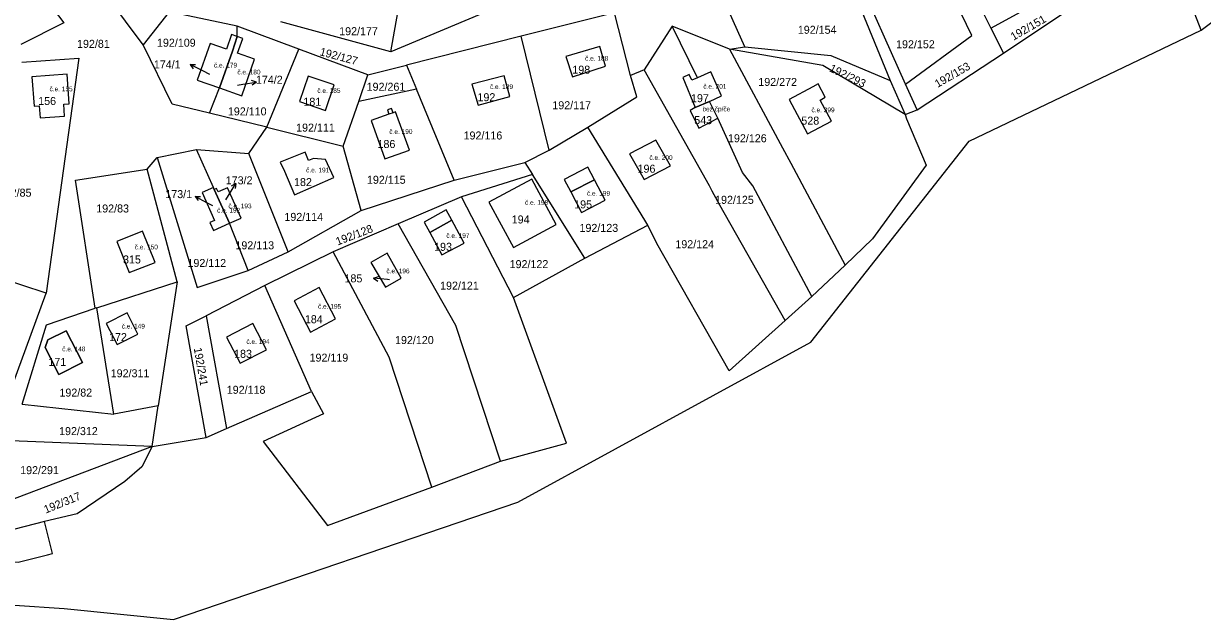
# Model space of a CAD drawing. Extents: x -887272 to -880188, y -1026687 to -1021896.
# Drawn here: x -882333.3 to -882082.9, y -1024320.7 to -1024194 of the extents above; entities that cross this region are included whole.
import ezdxf

# ---------------------------------------------------------------- set-up
doc = ezdxf.new("R2010")
doc.units = 0
for name, color, linetype in [('Definiční body', 7, 'Continuous'), ('Hranice parcel', 7, 'Continuous'), ('Parcelní čísla', 7, 'Continuous'), ('Polygon budovy', 7, 'Continuous'), ('Pop  PČ popisy', 7, 'Continuous'), ('Vnitřní kresba', 7, 'Continuous')]:
    doc.layers.add(name, color=color, linetype=linetype)

msp = doc.modelspace()

# ---------------------------------------------------------------- linework, layer by layer
at = {"layer": 'Hranice parcel'}
for p, q in [((-882137.35, -1024175.98), (-882127.83, -1024194.96)), ((-882083.16, -1024195.4), (-882090.34, -1024176.88)), ((-882255.25, -1024200.01), (-882252.31, -1024183.68)), ((-882127.83, -1024194.96), (-882110.47, -1024185.49)), ((-882083.16, -1024195.4), (-882069.52, -1024185.2)), ((-882307.87, -1024198.55), (-882315.45, -1024188.28)), ((-882125.14, -1024200.32), (-882108.68, -1024189.29)), ((-882255.25, -1024200.01), (-882278.63, -1024193.63)), ((-882236.46, -1024192.13), (-882255.25, -1024200.01)), ((-882207.74, -1024191.74), (-882227.58, -1024196.72)), ((-882204.37, -1024205.08), (-882207.74, -1024191.74)), ((-882287.91, -1024196.76), (-882287.91, -1024194.55)), ((-882274.77, -1024199.44), (-882287.91, -1024194.55)), ((-882195.51, -1024194.55), (-882201.44, -1024203.82)), ((-882183.3, -1024199.45), (-882195.51, -1024194.55)), ((-882190.09, -1024205.51), (-882195.51, -1024194.55)), ((-882127.83, -1024194.96), (-882125.14, -1024200.32)), ((-882227.58, -1024196.72), (-882251.93, -1024202.84)), ((-882221.64, -1024220.93), (-882227.58, -1024196.72)), ((-882183.3, -1024199.45), (-882180.08, -1024198.94)), ((-882333.65, -1024202.21), (-882321.52, -1024201.38)), ((-882321.52, -1024201.38), (-882328.48, -1024251.3)), ((-882281.59, -1024216.03), (-882274.77, -1024199.44)), ((-882260.11, -1024204.89), (-882274.77, -1024199.44)), ((-882143.48, -1024212.36), (-882125.14, -1024200.32)), ((-882260.11, -1024204.89), (-882251.93, -1024202.84)), ((-882251.93, -1024202.84), (-882249.83, -1024207.92)), ((-882201.44, -1024203.82), (-882204.37, -1024205.08)), ((-882262.06, -1024210.54), (-882260.11, -1024204.89)), ((-882149.19, -1024206.14), (-882145.98, -1024213.34)), ((-882293.75, -1024213.08), (-882291.66, -1024207.69)), ((-882249.83, -1024207.92), (-882262.06, -1024210.54)), ((-882241.79, -1024227.32), (-882249.83, -1024207.92)), ((-882143.48, -1024212.36), (-882145.92, -1024206.9)), ((-882265.36, -1024220.09), (-882262.06, -1024210.54)), ((-882190.63, -1024211.87), (-882187.6, -1024210.54)), ((-882185.83, -1024214.12), (-882187.6, -1024210.54)), ((-882281.59, -1024216.03), (-882293.75, -1024213.08)), ((-882145.98, -1024213.34), (-882143.48, -1024212.36)), ((-882145.98, -1024213.34), (-882145.75, -1024214.26)), ((-882285.44, -1024221.62), (-882281.59, -1024216.03)), ((-882281.59, -1024216.03), (-882265.36, -1024220.09)), ((-882221.64, -1024220.93), (-882213.38, -1024216.04)), ((-882180.56, -1024225.66), (-882185.83, -1024214.12)), ((-882304.86, -1024222.45), (-882296.53, -1024220.75)), ((-882292.94, -1024228.83), (-882296.53, -1024220.75)), ((-882296.53, -1024220.75), (-882285.44, -1024221.62)), ((-882261.58, -1024233.71), (-882265.36, -1024220.09)), ((-882226.76, -1024223.54), (-882221.64, -1024220.93)), ((-882307, -1024224.99), (-882304.86, -1024222.45)), ((-882277.04, -1024242.53), (-882285.44, -1024221.62)), ((-882241.79, -1024227.32), (-882226.76, -1024223.54)), ((-882226.76, -1024223.54), (-882225.17, -1024226.09)), ((-882300.66, -1024248.91), (-882307, -1024224.99)), ((-882225.17, -1024226.09), (-882240.26, -1024230.81)), ((-882214.06, -1024243.9), (-882225.17, -1024226.09)), ((-882292.75, -1024229.25), (-882292.94, -1024228.83)), ((-882261.58, -1024233.71), (-882241.79, -1024227.32)), ((-882289.52, -1024236.46), (-882292.75, -1024229.25)), ((-882240.26, -1024230.81), (-882253.67, -1024236.56)), ((-882229.17, -1024252.22), (-882240.26, -1024230.81)), ((-882277.04, -1024242.53), (-882261.58, -1024233.71)), ((-882285.58, -1024246.47), (-882289.52, -1024236.46)), ((-882253.67, -1024236.56), (-882267.53, -1024242.5)), ((-882214.06, -1024243.9), (-882200.68, -1024236.89)), ((-882285.58, -1024246.47), (-882277.04, -1024242.53)), ((-882267.53, -1024242.5), (-882282.01, -1024249.71)), ((-882229.17, -1024252.22), (-882214.06, -1024243.9)), ((-882158.78, -1024245.34), (-882165.85, -1024252.03)), ((-882328.48, -1024251.3), (-882341.03, -1024247.16)), ((-882317.71, -1024254.4), (-882300.66, -1024248.91)), ((-882300.66, -1024248.91), (-882304.64, -1024275.27)), ((-882339.9, -1024282.5), (-882328.48, -1024251.3)), ((-882282.01, -1024249.71), (-882294.5, -1024256.1)), ((-882272.1, -1024272.18), (-882282.01, -1024249.71)), ((-882165.85, -1024252.03), (-882171.52, -1024257.13)), ((-882317.71, -1024254.4), (-882318.06, -1024254.51)), ((-882314.06, -1024277.04), (-882317.71, -1024254.4)), ((-882294.5, -1024256.1), (-882290.13, -1024280.09)), ((-882287.25, -1024266.21), (-882281.69, -1024263.34)), ((-882290.13, -1024280.09), (-882272.1, -1024272.18)), ((-882333.57, -1024274.9), (-882314.06, -1024277.04)), ((-882304.64, -1024275.27), (-882314.06, -1024277.04)), ((-882305.94, -1024283.91), (-882304.64, -1024275.27)), ((-882294.5, -1024282), (-882290.13, -1024280.09)), ((-882305.94, -1024283.91), (-882340.7, -1024297.09)), ((-882305.94, -1024283.91), (-882335.99, -1024282.71)), ((-882305.94, -1024283.91), (-882294.5, -1024282)), ((-882246.57, -1024292.54), (-882231.98, -1024287))]:
    msp.add_line(p, q, dxfattribs=at)
for points in [[(-882180.08, -1024198.94), (-882186.61, -1024184.38), (-882170.75, -1024175.81), (-882159.27, -1024181.5), (-882149.19, -1024206.14)], [(-882145.92, -1024206.9), (-882156.65, -1024182.88), (-882141.11, -1024177.32)], [(-882145.92, -1024206.9), (-882131.84, -1024196.57), (-882141.11, -1024177.32)], [(-882334.7, -1024180.71), (-882324.68, -1024193.85), (-882333.83, -1024198.49)], [(-882287.91, -1024194.55), (-882302.33, -1024191.49), (-882307.87, -1024198.55)], [(-882425.59, -1024292.38), (-882421.44, -1024309.52), (-882387.34, -1024318.62), (-882335.2, -1024317.62), (-882324.6, -1024318.36), (-882301.38, -1024320.66), (-882228.26, -1024295.72), (-882166.04, -1024261.72), (-882132.4, -1024219.02), (-882083.16, -1024195.4)], [(-882287.91, -1024196.76), (-882289.09, -1024196.35), (-882290.17, -1024199.42), (-882293.65, -1024198.24), (-882296.39, -1024206.02), (-882291.66, -1024207.69)], [(-882293.75, -1024213.08), (-882301.69, -1024211.15), (-882307.87, -1024198.55)], [(-882291.66, -1024207.69), (-882288.91, -1024199.91), (-882287.91, -1024196.76)], [(-882291.66, -1024207.69), (-882286.93, -1024209.36), (-882284.18, -1024201.58), (-882287.81, -1024200.29), (-882286.72, -1024197.18), (-882287.91, -1024196.76)], [(-882210.86, -1024198.88), (-882218.06, -1024201), (-882216.7, -1024205.32), (-882209.64, -1024203.1), (-882210.86, -1024198.88)], [(-882180.08, -1024198.94), (-882161.77, -1024200.83), (-882149.19, -1024206.14)], [(-882145.98, -1024213.34), (-882163.48, -1024202.95), (-882183.3, -1024199.45)], [(-882183.3, -1024199.45), (-882172.08, -1024220.45), (-882170.3, -1024223.69), (-882158.78, -1024245.34)], [(-882171.52, -1024257.13), (-882185.35, -1024232.63), (-882186.97, -1024229.61), (-882187.58, -1024228.52), (-882201.44, -1024203.82)], [(-882324.73, -1024211.15), (-882323.57, -1024211.07), (-882324.01, -1024204.8), (-882331.48, -1024205.32), (-882331.04, -1024211.59), (-882329.92, -1024211.51), (-882329.75, -1024214.03), (-882324.56, -1024213.66), (-882324.73, -1024211.15)], [(-882269.12, -1024212.48), (-882267.28, -1024207.04), (-882272.82, -1024205.16), (-882274.66, -1024210.6), (-882269.12, -1024212.48)], [(-882238.06, -1024206.92), (-882236.68, -1024211.34), (-882229.98, -1024209.54), (-882231.17, -1024205.1), (-882238.06, -1024206.92)], [(-882213.38, -1024216.04), (-882203.01, -1024209.61), (-882204.37, -1024205.08)], [(-882190.09, -1024205.51), (-882191.34, -1024206.06), (-882191.87, -1024204.86), (-882193.25, -1024205.47), (-882190.63, -1024211.87)], [(-882187.6, -1024210.54), (-882185, -1024209.4), (-882187.26, -1024204.26), (-882190.09, -1024205.51)], [(-882164.08, -1024210.28), (-882162.97, -1024209.68), (-882164.51, -1024206.83), (-882165.62, -1024207.44), (-882170.68, -1024210.17), (-882166.73, -1024217.47), (-882161.67, -1024214.72), (-882164.08, -1024210.28)], [(-882251.3, -1024220.9), (-882254.23, -1024212.75), (-882254.79, -1024212.95), (-882255.11, -1024212.06), (-882255.98, -1024212.38), (-882255.66, -1024213.27), (-882259.45, -1024214.63), (-882256.52, -1024222.78), (-882251.3, -1024220.9)], [(-882190.63, -1024211.87), (-882191.71, -1024212.5), (-882189.8, -1024216.26), (-882185.83, -1024214.12)], [(-882200.68, -1024236.89), (-882201.33, -1024235.82), (-882213.38, -1024216.04)], [(-882145.75, -1024214.26), (-882141.56, -1024224.13), (-882152.95, -1024239.76), (-882158.78, -1024245.34)], [(-882201.44, -1024227.17), (-882195.88, -1024224.22), (-882199, -1024218.76), (-882204.57, -1024221.7), (-882201.44, -1024227.17)], [(-882272.74, -1024223.14), (-882273.48, -1024221.33), (-882278.76, -1024223.45), (-882277.87, -1024225.35), (-882275.68, -1024230.39), (-882267.34, -1024226.76), (-882269.11, -1024222.93), (-882271.67, -1024222.67), (-882272.74, -1024223.14)], [(-882304.86, -1024222.45), (-882296.39, -1024250.09), (-882285.58, -1024246.47)], [(-882318.06, -1024254.51), (-882322.2, -1024227.27), (-882307, -1024224.99)], [(-882212, -1024227.22), (-882213.39, -1024224.56), (-882218.41, -1024227.12), (-882217.04, -1024229.79), (-882214.79, -1024234.19), (-882209.75, -1024231.53), (-882212, -1024227.22)], [(-882165.85, -1024252.03), (-882178.37, -1024228.51), (-882180.56, -1024225.66)], [(-882292.94, -1024228.83), (-882295.35, -1024229.9), (-882292.71, -1024235.84), (-882293.66, -1024236.26), (-882292.91, -1024237.96), (-882289.52, -1024236.46)], [(-882289.52, -1024236.46), (-882287.04, -1024235.36), (-882289.91, -1024228.89), (-882291.94, -1024229.79), (-882292.27, -1024229.04), (-882292.75, -1024229.25)], [(-882229.23, -1024241.61), (-882220.13, -1024236.69), (-882225.33, -1024227.08), (-882234.44, -1024231.98), (-882229.23, -1024241.61)], [(-882246.98, -1024238.4), (-882244.42, -1024243.2), (-882239.66, -1024240.66), (-882242.29, -1024235.83), (-882243.49, -1024233.63), (-882248.15, -1024236.2), (-882246.98, -1024238.4)], [(-882313.46, -1024240.32), (-882310.8, -1024246.9), (-882305.32, -1024244.78), (-882307.99, -1024238.11), (-882313.46, -1024240.32)], [(-882231.98, -1024287), (-882241.44, -1024258.19), (-882253.67, -1024236.56)], [(-882171.52, -1024257.13), (-882183.4, -1024267.82), (-882198.74, -1024240.75), (-882200.68, -1024236.89)], [(-882246.57, -1024292.54), (-882255.59, -1024264.95), (-882267.53, -1024242.5)], [(-882259.52, -1024244.82), (-882256.38, -1024250.06), (-882253.04, -1024248.16), (-882256.04, -1024242.8), (-882259.52, -1024244.82)], [(-882272.32, -1024259.58), (-882266.97, -1024256.76), (-882270.46, -1024250.13), (-882275.81, -1024252.95), (-882272.32, -1024259.58)], [(-882231.98, -1024287), (-882217.96, -1024283.21), (-882229.17, -1024252.22)], [(-882333.57, -1024274.9), (-882328.36, -1024258.07), (-882318.06, -1024254.51)], [(-882308.98, -1024260.01), (-882311.25, -1024255.5), (-882315.71, -1024257.75), (-882313.39, -1024262.23), (-882308.98, -1024260.01)], [(-882294.5, -1024282), (-882298.74, -1024258.26), (-882294.5, -1024256.1)], [(-882281.69, -1024263.34), (-882284.56, -1024257.78), (-882290.12, -1024260.65), (-882287.25, -1024266.21)], [(-882320.76, -1024266.08), (-882325.76, -1024268.62), (-882328.68, -1024262.86), (-882328.13, -1024261.26), (-882324.19, -1024259.33), (-882320.76, -1024266.08)], [(-882272.1, -1024272.18), (-882269.56, -1024276.98), (-882282.34, -1024282.85), (-882268.67, -1024300.71), (-882246.57, -1024292.54)], [(-882305.94, -1024283.91), (-882308.16, -1024288.24), (-882311.77, -1024291.31), (-882321.85, -1024298.23), (-882328.81, -1024299.87)], [(-882354.68, -1024304.32), (-882351.37, -1024305.83), (-882343, -1024308.06), (-882334.42, -1024308.5), (-882328.14, -1024306.91), (-882327.09, -1024306.65), (-882328.81, -1024299.87)], [(-882328.81, -1024299.87), (-882335.11, -1024301.46), (-882341.68, -1024300.07)]]:
    msp.add_lwpolyline(points, dxfattribs=at)
at = {"layer": 'Polygon budovy'}
for points in [[(-882293.65, -1024198.24), (-882296.39, -1024206.02), (-882291.66, -1024207.69), (-882288.91, -1024199.91), (-882287.91, -1024196.76), (-882289.09, -1024196.35), (-882290.17, -1024199.42)], [(-882291.66, -1024207.69), (-882286.93, -1024209.36), (-882284.18, -1024201.58), (-882287.81, -1024200.29), (-882286.72, -1024197.18), (-882287.91, -1024196.76), (-882288.91, -1024199.91)], [(-882218.06, -1024201), (-882216.7, -1024205.32), (-882209.64, -1024203.1), (-882210.86, -1024198.88)], [(-882331.04, -1024211.59), (-882329.92, -1024211.51), (-882329.75, -1024214.03), (-882324.56, -1024213.66), (-882324.73, -1024211.15), (-882323.57, -1024211.07), (-882324.01, -1024204.8), (-882331.48, -1024205.32)], [(-882267.28, -1024207.04), (-882272.82, -1024205.16), (-882274.66, -1024210.6), (-882269.12, -1024212.48)], [(-882229.98, -1024209.54), (-882231.17, -1024205.1), (-882238.06, -1024206.92), (-882236.68, -1024211.34)], [(-882190.09, -1024205.51), (-882191.34, -1024206.06), (-882191.87, -1024204.86), (-882193.25, -1024205.47), (-882190.63, -1024211.87), (-882187.6, -1024210.54), (-882185, -1024209.4), (-882187.26, -1024204.26)], [(-882170.68, -1024210.17), (-882166.73, -1024217.47), (-882161.67, -1024214.72), (-882164.08, -1024210.28), (-882162.97, -1024209.68), (-882164.51, -1024206.83), (-882165.62, -1024207.44)], [(-882190.63, -1024211.87), (-882191.71, -1024212.5), (-882189.8, -1024216.26), (-882185.83, -1024214.12), (-882187.6, -1024210.54)], [(-882259.45, -1024214.63), (-882256.52, -1024222.78), (-882251.3, -1024220.9), (-882254.23, -1024212.75), (-882254.79, -1024212.95), (-882255.66, -1024213.27)], [(-882195.88, -1024224.22), (-882199, -1024218.76), (-882204.57, -1024221.7), (-882201.44, -1024227.17)], [(-882271.67, -1024222.67), (-882272.74, -1024223.14), (-882273.48, -1024221.33), (-882278.76, -1024223.45), (-882277.87, -1024225.35), (-882275.68, -1024230.39), (-882267.34, -1024226.76), (-882269.11, -1024222.93)], [(-882292.91, -1024237.96), (-882289.52, -1024236.46), (-882292.75, -1024229.25), (-882292.94, -1024228.83), (-882295.35, -1024229.9), (-882292.71, -1024235.84), (-882293.66, -1024236.26)], [(-882292.75, -1024229.25), (-882289.52, -1024236.46), (-882287.04, -1024235.36), (-882289.91, -1024228.89), (-882291.94, -1024229.79), (-882292.27, -1024229.04)], [(-882234.44, -1024231.98), (-882229.23, -1024241.61), (-882220.13, -1024236.69), (-882225.33, -1024227.08)], [(-882217.04, -1024229.79), (-882214.79, -1024234.19), (-882209.75, -1024231.53), (-882212, -1024227.22)], [(-882244.42, -1024243.2), (-882239.66, -1024240.66), (-882242.29, -1024235.83), (-882246.98, -1024238.4)], [(-882305.32, -1024244.78), (-882307.99, -1024238.11), (-882313.46, -1024240.32), (-882310.8, -1024246.9)], [(-882256.04, -1024242.8), (-882259.52, -1024244.82), (-882256.38, -1024250.06), (-882253.04, -1024248.16)], [(-882266.97, -1024256.76), (-882270.46, -1024250.13), (-882275.81, -1024252.95), (-882272.32, -1024259.58)], [(-882313.39, -1024262.23), (-882308.98, -1024260.01), (-882311.25, -1024255.5), (-882315.71, -1024257.75)], [(-882287.25, -1024266.21), (-882281.69, -1024263.34), (-882284.56, -1024257.78), (-882290.12, -1024260.65)], [(-882324.19, -1024259.33), (-882328.13, -1024261.26), (-882328.68, -1024262.86), (-882325.76, -1024268.62), (-882320.76, -1024266.08)]]:
    msp.add_lwpolyline(points, close=True, dxfattribs=at)
at = {"layer": 'Pop  PČ popisy'}
for p, q in [((-882295.21, -1024204.08), (-882297.88, -1024202.72)), ((-882297.88, -1024202.72), (-882296.76, -1024202.73)), ((-882297.88, -1024202.72), (-882297.22, -1024203.62)), ((-882293.67, -1024204.87), (-882295.21, -1024204.08)), ((-882286.72, -1024206.92), (-882283.76, -1024206.45)), ((-882283.76, -1024206.45), (-882284.82, -1024206.11)), ((-882283.76, -1024206.45), (-882284.67, -1024207.1)), ((-882287.8, -1024207.09), (-882286.72, -1024206.92)), ((-882289.75, -1024230.54), (-882288.2, -1024227.97)), ((-882288.2, -1024227.97), (-882289.15, -1024228.57)), ((-882288.2, -1024227.97), (-882288.29, -1024229.08)), ((-882294.16, -1024232.15), (-882296.81, -1024230.74)), ((-882296.81, -1024230.74), (-882295.69, -1024230.77)), ((-882296.81, -1024230.74), (-882296.16, -1024231.65)), ((-882290.3, -1024231.46), (-882289.75, -1024230.54)), ((-882293.08, -1024232.72), (-882294.16, -1024232.15)), ((-882258.93, -1024248.16), (-882257.89, -1024247.75)), ((-882255.94, -1024248.42), (-882258.93, -1024248.16)), ((-882258.93, -1024248.16), (-882257.98, -1024248.74)), ((-882255.56, -1024248.45), (-882255.94, -1024248.42))]:
    msp.add_line(p, q, dxfattribs=at)
at = {"layer": 'Vnitřní kresba'}
for p, q in [((-882254.79, -1024212.95), (-882255.66, -1024213.27)), ((-882217.04, -1024229.79), (-882212, -1024227.22)), ((-882246.98, -1024238.4), (-882242.29, -1024235.83))]:
    msp.add_line(p, q, dxfattribs=at)

# ---------------------------------------------------------------- texts
at = {"layer": 'Definiční body'}
for s, p in [('č.e. 188', (-882213.99, -1024201.9)), ('č.e. 179', (-882292.82, -1024203.35)), ('č.e. 180', (-882287.84, -1024204.82)), ('č.e. 155', (-882327.74, -1024208.4)), ('č.e. 185', (-882270.86, -1024208.75)), ('č.e. 189', (-882234.21, -1024207.91)), ('č.e. 201', (-882188.88, -1024207.87)), ('bez čp/če', (-882189.06, -1024212.67)), ('č.e. 399', (-882165.91, -1024212.86)), ('č.e. 190', (-882255.57, -1024217.47)), ('č.e. 200', (-882200.32, -1024222.99)), ('č.e. 191', (-882273.24, -1024225.64)), ('č.e. 198', (-882226.75, -1024232.53)), ('č.e. 199', (-882213.6, -1024230.59)), ('č.e. 192', (-882292.15, -1024234.19)), ('č.e. 193', (-882289.74, -1024233.27)), ('č.e. 197', (-882243.46, -1024239.57)), ('č.e. 150', (-882309.64, -1024242)), ('č.e. 196', (-882256.19, -1024247.09)), ('č.e. 195', (-882270.71, -1024254.62)), ('č.e. 149', (-882312.4, -1024258.83)), ('č.e. 194', (-882285.92, -1024262.09)), ('č.e. 148', (-882325.05, -1024263.67))]:
    msp.add_text(s, height=1, dxfattribs=at).set_placement(p)
at = {"layer": 'Parcelní čísla'}
for s, rotation, p in [('192/151', 30, (-882123.01, -1024197.67)), ('192/127', 345, (-882270.48, -1024200.72)), ('192/293', 334, (-882162.28, -1024204.08)), ('192/153', 30, (-882139.12, -1024207.7)), ('192/128', 21, (-882266.56, -1024241.2)), ('192/241', 280, (-882297.12, -1024263.03)), ('192/317', 22, (-882328.54, -1024298.17))]:
    msp.add_text(s, height=1.7, rotation=rotation, dxfattribs=at).set_placement(p)
for s, p in [('192/177', (-882266.22, -1024196.48)), ('192/154', (-882168.81, -1024196.18)), ('192/81', (-882321.9, -1024199.17)), ('192/109', (-882304.92, -1024198.93)), ('192/152', (-882147.94, -1024199.26)), ('174/1', (-882305.59, -1024203.56)), ('198', (-882216.7, -1024204.66)), ('174/2', (-882283.91, -1024206.8)), ('192/272', (-882177.2, -1024207.27)), ('192/261', (-882260.39, -1024208.29)), ('192', (-882236.85, -1024210.51)), ('156', (-882330.15, -1024211.32)), ('181', (-882273.82, -1024211.47)), ('192/117', (-882220.95, -1024212.22)), ('197', (-882191.5, -1024210.72)), ('192/110', (-882289.86, -1024213.53)), ('543', (-882190.8, -1024215.39)), ('528', (-882168.06, -1024215.49)), ('192/111', (-882275.37, -1024216.98)), ('186', (-882258.08, -1024220.46)), ('192/116', (-882239.8, -1024218.65)), ('192/126', (-882183.64, -1024219.24)), ('196', (-882202.85, -1024225.71)), ('173/2', (-882290.32, -1024228.18)), ('192/115', (-882260.32, -1024228.06)), ('182', (-882275.81, -1024228.55)), ('192/85', (-882338.53, -1024230.81)), ('173/1', (-882303.15, -1024231.11)), ('192/125', (-882186.38, -1024232.32)), ('192/83', (-882317.82, -1024234.16)), ('195', (-882216.31, -1024233.29)), ('192/114', (-882277.86, -1024235.95)), ('194', (-882229.58, -1024236.49)), ('192/123', (-882215.18, -1024238.29)), ('192/113', (-882288.26, -1024241.99)), ('193', (-882246.06, -1024242.31)), ('192/124', (-882194.82, -1024241.76)), ('315', (-882312.13, -1024245)), ('192/112', (-882298.45, -1024245.75)), ('192/122', (-882230.02, -1024245.99)), ('185', (-882265.09, -1024249.02)), ('192/121', (-882244.79, -1024250.57)), ('184', (-882273.51, -1024257.7)), ('172', (-882315.1, -1024261.49)), ('192/120', (-882254.36, -1024262.13)), ('183', (-882288.54, -1024265.05)), ('171', (-882327.99, -1024266.78)), ('192/119', (-882272.51, -1024265.87)), ('192/311', (-882314.75, -1024269.19)), ('192/82', (-882325.64, -1024273.29)), ('192/118', (-882290.1, -1024272.7)), ('192/312', (-882325.71, -1024281.48)), ('192/291', (-882333.98, -1024289.78))]:
    msp.add_text(s, height=1.7, dxfattribs=at).set_placement(p)

doc.saveas('drawing.dxf')
